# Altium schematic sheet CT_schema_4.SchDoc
size 349 x 342 mm
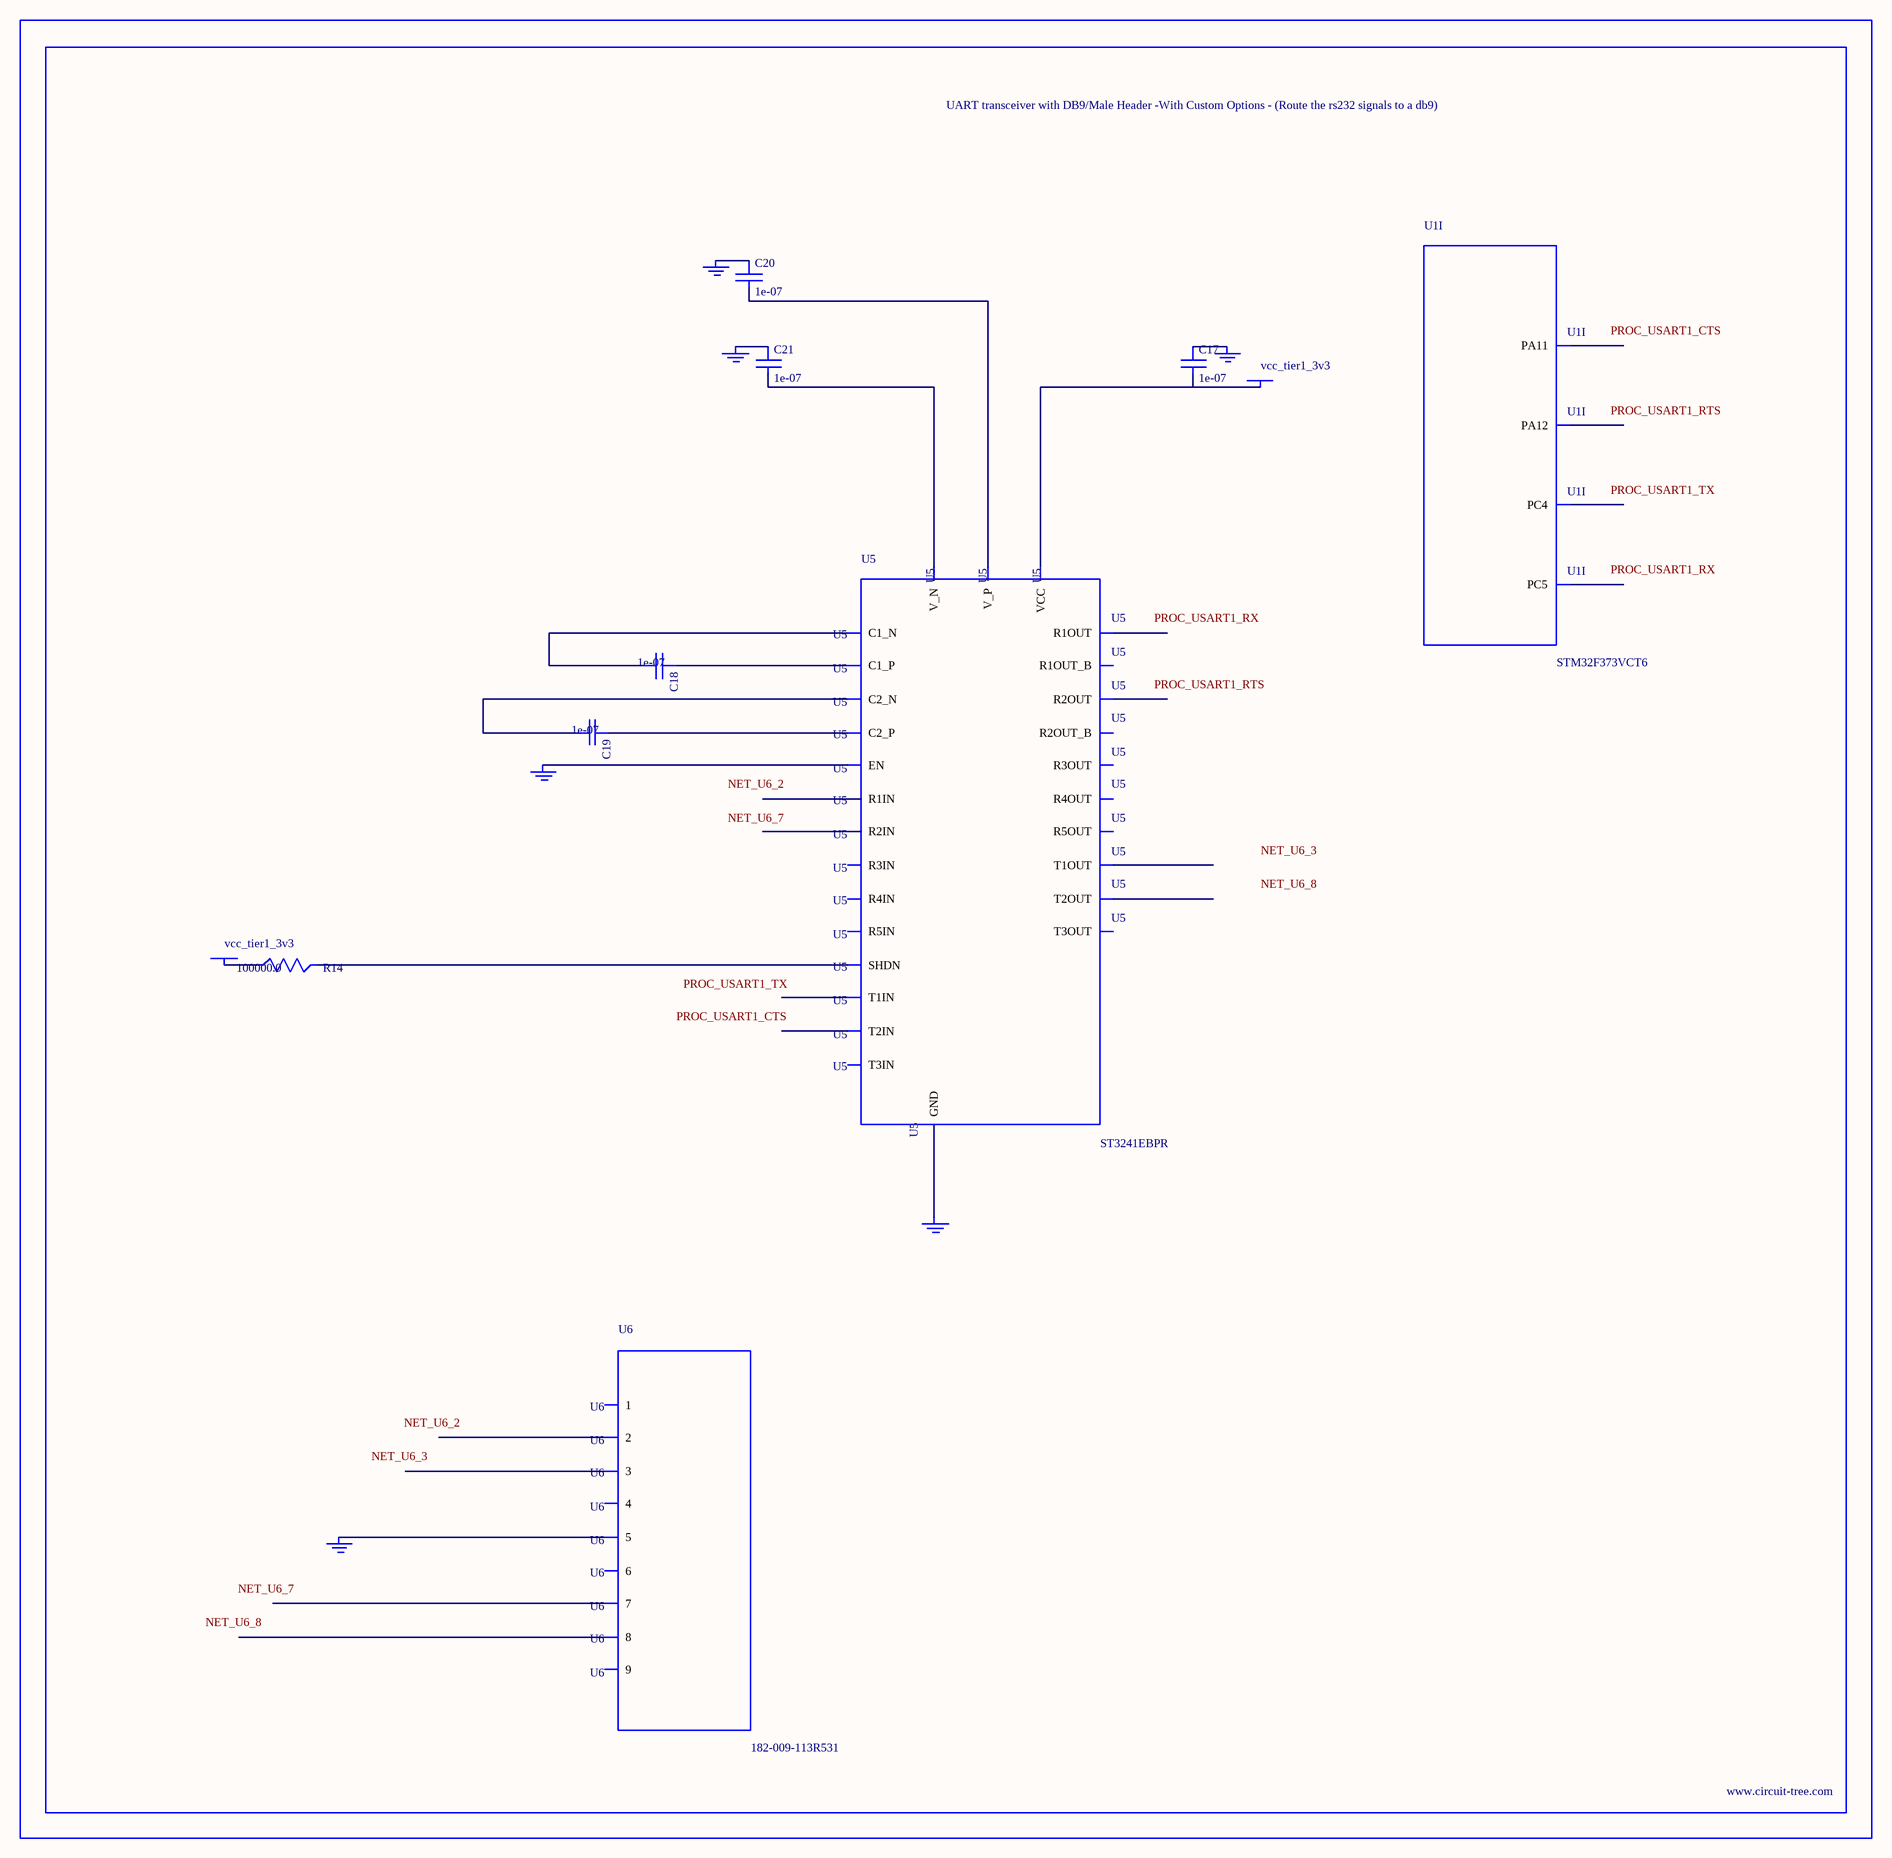
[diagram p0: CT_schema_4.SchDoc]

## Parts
BORDER3  (no value)
C17  1e-07  [C0402]
C18  1e-07  [C0402]
C19  1e-07  [C0402]
C20  1e-07  [C0402]
C21  1e-07  [C0402]
GND_INSTANCE_3_0  (no value)
GND_INSTANCE_3_1  (no value)
GND_INSTANCE_3_2  (no value)
GND_INSTANCE_3_3  (no value)
GND_INSTANCE_3_4  (no value)
GND_INSTANCE_3_5  (no value)
POWER_INSTANCE_3_0  vcc_tier1_3v3
POWER_INSTANCE_3_1  vcc_tier1_3v3
R14  100000.0  [R0603]
U1  STM32F373VCT6  [LQFP100]  (part I of 10)
U5  ST3241EBPR  [SSOP-28]
U6  182-009-113R531  [182-009-MALE]

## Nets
NetC17_1: C17.1 GND_INSTANCE_3_2.0(GND)
NetC17_2: C17.2 POWER_INSTANCE_3_1.0(PWR) U5.26(VCC)
NetC18_1: C18.1 U5.28(C1_P)
NetC18_2: C18.2 U5.24(C1_N)
NetC19_1: C19.1 U5.1(C2_P)
NetC19_2: C19.2 U5.2(C2_N)
NetC20_1: C20.1 GND_INSTANCE_3_3.0(GND)
NetC20_2: C20.2 U5.27(V_P)
NetC21_1: C21.1 GND_INSTANCE_3_0.0(GND)
NetC21_2: C21.2 U5.3(V_N)
NetGND_INSTANCE_3_1_0: GND_INSTANCE_3_1.0(GND) U5.23(EN)
NetGND_INSTANCE_3_4_0: GND_INSTANCE_3_4.0(GND) U5.25(GND)
NetGND_INSTANCE_3_5_0: GND_INSTANCE_3_5.0(GND) U6.5
NetPOWER_INSTANCE_3_0_0: POWER_INSTANCE_3_0.0(PWR) R14.1
NetR14_2: R14.2 U5.22(SHDN)

Not connected (* = marked no-connect by the designer): U1 33(PC4) 34(PC5) 70(PA11) 71(PA12); U5 4(R1IN) 5(R2IN) 6(R3IN) 7(R4IN) 8(R5IN) 9(T1OUT) 10(T2OUT) 11(T3OUT) 12(T3IN) 13(T2IN) 14(T1IN) 15(R5OUT) 16(R4OUT) 17(R3OUT) 18(R2OUT) 19(R1OUT) 20(R2OUT_B) 21(R1OUT_B); U6 1 2 3 4 6 7 8 9

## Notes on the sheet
- Labels drawn without touching a wire or pin: NET_U6_2, NET_U6_3, NET_U6_7, NET_U6_8, PROC_USART1_CTS, PROC_USART1_RTS, PROC_USART1_RX, PROC_USART1_TX

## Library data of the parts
BORDER3 = BORDER_PAGE3
C17-C21 = C0402C104K3RACTU
GND_INSTANCE_3_0-GND_INSTANCE_3_5 = GND
POWER_INSTANCE_3_0 POWER_INSTANCE_3_1 = PWR
R14 = RC0603JR-07100KL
